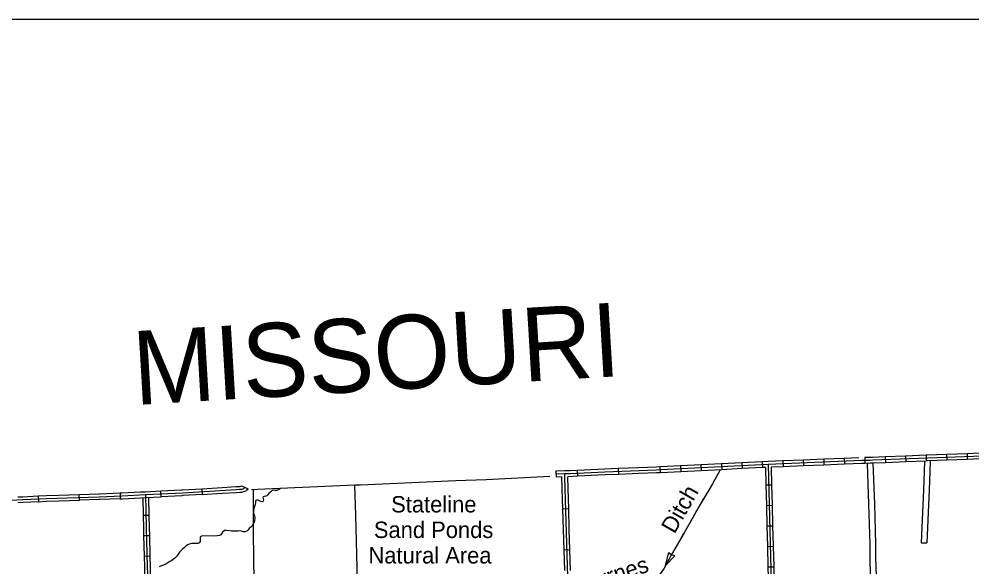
# Model space of a CAD drawing. Extents: x 1164457 to 1439835, y 1590918 to 1773502.
# Drawn here: x 1283501 to 1308056, y 1664462 to 1678582 of the extents above; entities that cross this region are included whole.
import ezdxf

# ---------------------------------------------------------------- set-up
doc = ezdxf.new("R2010")
doc.units = 0
for name, color, linetype in [('Level 1', 7, 'Continuous'), ('Level 30', 7, 'Continuous'), ('Level 31', 7, 'Continuous'), ('Level 32', 7, 'Continuous'), ('Level 35', 7, 'Continuous'), ('Level 43', 7, 'Continuous'), ('Level 45', 7, 'Continuous'), ('Level 46', 7, 'Continuous'), ('Level 7', 7, 'Continuous'), ('R_Draft', 7, 'Continuous')]:
    doc.layers.add(name, color=color, linetype=linetype)

msp = doc.modelspace()

# ---------------------------------------------------------------- linework, layer by layer
at = {"layer": 'Level 1'}
msp.add_lwpolyline([(1297182, 1666796), (1295539, 1666710), (1294754, 1666683), (1292299, 1666571), (1292152, 1666566), (1289647, 1666456), (1289493, 1666448)], dxfattribs=at)
at = {"layer": 'Level 31'}
for p, q in [((1286103, 1666369), (1286110, 1666219)), ((1287165, 1666272), (1287158, 1666421)), ((1288211, 1666479), (1288220, 1666329)), ((1283992, 1666292), (1284000, 1666143)), ((1285054, 1666180), (1285049, 1666330))]:
    msp.add_line(p, q, dxfattribs=at)
for points in [[(1278722, 1665984), (1279927, 1666021), (1281431, 1666097), (1281840, 1666107), (1282171, 1666122), (1283600, 1666197), (1284208, 1666228), (1285566, 1666271), (1286152, 1666296), (1286763, 1666327), (1287718, 1666374), (1289093, 1666457), (1289185, 1666463)], [(1285576, 1666347), (1286103, 1666369)], [(1286103, 1666369), (1286149, 1666371), (1286630, 1666395)], [(1286630, 1666395), (1286759, 1666402), (1287158, 1666421)], [(1287158, 1666421), (1287685, 1666448)], [(1287685, 1666448), (1287714, 1666449), (1288211, 1666479)], [(1288211, 1666479), (1288738, 1666511)], [(1288738, 1666511), (1289089, 1666532), (1289181, 1666537), (1289218, 1666540), (1289231, 1666549), (1289401, 1666471)], [(1288747, 1666361), (1289097, 1666382), (1289190, 1666388), (1289238, 1666391), (1289269, 1666397), (1289290, 1666404), (1289343, 1666426), (1289372, 1666445), (1289401, 1666471)], [(1289185, 1666463), (1289228, 1666465), (1289251, 1666470), (1289273, 1666477), (1289294, 1666487), (1289307, 1666504)], [(1283465, 1666265), (1283596, 1666272), (1283992, 1666292)], [(1284000, 1666143), (1283604, 1666122), (1283473, 1666115)], [(1283992, 1666292), (1284205, 1666303), (1284521, 1666313)], [(1284000, 1666143), (1284211, 1666153), (1284526, 1666163)], [(1284521, 1666313), (1285049, 1666330)], [(1284526, 1666163), (1285054, 1666180)], [(1285049, 1666330), (1285563, 1666346), (1285576, 1666347)], [(1285582, 1666197), (1285568, 1666196), (1285054, 1666180)], [(1286110, 1666219), (1285582, 1666197)], [(1286110, 1666219), (1286156, 1666221), (1286638, 1666245)], [(1286638, 1666245), (1286766, 1666252), (1287165, 1666272)], [(1287692, 1666298), (1287165, 1666272)], [(1288220, 1666329), (1287722, 1666299), (1287692, 1666298)], [(1288220, 1666329), (1288747, 1666361)]]:
    msp.add_lwpolyline(points, dxfattribs=at)
at = {"layer": 'Level 32'}
for p, q in [((1307403, 1667361), (1307409, 1667211)), ((1307931, 1667381), (1307936, 1667231)), ((1301599, 1667118), (1301607, 1666968)), ((1302127, 1667144), (1302134, 1666995)), ((1302654, 1667171), (1302661, 1667021)), ((1303182, 1667194), (1303188, 1667044)), ((1303710, 1667216), (1303716, 1667066)), ((1304237, 1667238), (1304243, 1667088)), ((1304765, 1667260), (1304771, 1667110)), ((1305293, 1667280), (1305297, 1667130)), ((1305820, 1667298), (1305826, 1667149)), ((1306348, 1667320), (1306354, 1667170)), ((1306875, 1667341), (1306881, 1667192)), ((1300016, 1667038), (1300026, 1666888)), ((1300545, 1667065), (1300552, 1666915)), ((1301072, 1667091), (1301079, 1666941)), ((1302745, 1666574), (1302895, 1666578)), ((1302758, 1666046), (1302908, 1666050)), ((1286698, 1665797), (1286848, 1665800)), ((1302771, 1665518), (1302921, 1665522)), ((1286709, 1665269), (1286859, 1665273)), ((1302785, 1664990), (1302934, 1664994)), ((1286723, 1664741), (1286872, 1664745)), ((1302798, 1664462), (1302948, 1664466))]:
    msp.add_line(p, q, dxfattribs=at)
for points in [[(1321119, 1667917), (1318832, 1667801), (1318254, 1667775), (1315826, 1667665), (1313323, 1667544), (1312931, 1667528), (1312880, 1667526), (1310607, 1667432), (1308095, 1667312), (1306907, 1667268), (1305501, 1667210), (1305435, 1667209), (1305218, 1667203), (1302807, 1667104), (1300037, 1666964), (1300001, 1666961)], [(1307403, 1667361), (1306904, 1667343), (1306875, 1667341)], [(1307931, 1667381), (1307403, 1667361)], [(1308457, 1667404), (1308092, 1667387), (1307931, 1667381)], [(1301599, 1667118), (1301072, 1667091)], [(1302127, 1667144), (1301599, 1667118)], [(1302654, 1667171), (1302127, 1667144)], [(1303182, 1667194), (1302803, 1667178), (1302654, 1667171)], [(1302807, 1667104), (1302959, 1661013), (1303033, 1658417), (1303054, 1657502), (1303073, 1656547), (1303091, 1655953), (1303095, 1655780), (1303144, 1653171), (1303204, 1650854), (1303207, 1650572)], [(1303710, 1667216), (1303182, 1667194)], [(1304237, 1667238), (1303710, 1667216)], [(1304765, 1667260), (1304237, 1667238)], [(1304771, 1667110), (1304243, 1667088)], [(1305144, 1667275), (1304765, 1667260)], [(1305297, 1667130), (1305220, 1667128), (1304771, 1667110)], [(1305820, 1667298), (1305498, 1667285), (1305433, 1667284), (1305293, 1667280)], [(1305826, 1667149), (1305503, 1667135), (1305437, 1667134), (1305297, 1667130)], [(1306348, 1667320), (1305820, 1667298)], [(1306354, 1667170), (1305826, 1667149)], [(1306875, 1667341), (1306348, 1667320)], [(1306881, 1667192), (1306354, 1667170)], [(1307409, 1667211), (1306910, 1667193), (1306881, 1667192)], [(1307936, 1667231), (1307409, 1667211)], [(1308464, 1667254), (1308099, 1667237), (1307936, 1667231)], [(1300545, 1667065), (1300033, 1667039), (1300016, 1667038)], [(1300552, 1666915), (1300042, 1666889), (1300026, 1666888)], [(1301072, 1667091), (1300545, 1667065)], [(1301079, 1666941), (1300552, 1666915)], [(1301607, 1666968), (1301079, 1666941)], [(1302134, 1666995), (1301607, 1666968)], [(1302661, 1667021), (1302134, 1666995)], [(1302734, 1667025), (1302661, 1667021)], [(1302734, 1667025), (1302745, 1666574)], [(1303188, 1667044), (1302884, 1667032)], [(1302884, 1667032), (1302895, 1666578)], [(1303716, 1667066), (1303188, 1667044)], [(1304243, 1667088), (1303716, 1667066)], [(1302745, 1666574), (1302758, 1666046)], [(1302895, 1666578), (1302908, 1666050)], [(1286689, 1666248), (1286698, 1665797)], [(1286763, 1666327), (1286779, 1665469), (1286805, 1664462), (1286808, 1664283)], [(1286839, 1666255), (1286848, 1665800)], [(1302758, 1666046), (1302771, 1665518)], [(1302908, 1666050), (1302921, 1665522)], [(1286698, 1665797), (1286704, 1665467), (1286709, 1665269)], [(1286848, 1665800), (1286854, 1665470), (1286859, 1665273)], [(1302771, 1665518), (1302785, 1664990)], [(1302921, 1665522), (1302934, 1664994)], [(1286709, 1665269), (1286723, 1664741)], [(1286859, 1665273), (1286872, 1664745)], [(1302785, 1664990), (1302798, 1664462)], [(1302934, 1664994), (1302948, 1664466)], [(1286723, 1664741), (1286730, 1664461), (1286733, 1664280), (1286737, 1664211)], [(1286872, 1664745), (1286880, 1664464), (1286883, 1664286), (1286887, 1664220)], [(1302798, 1664462), (1302811, 1663935)], [(1302948, 1664466), (1302961, 1663938)]]:
    msp.add_lwpolyline(points, dxfattribs=at)
at = {"layer": 'Level 35'}
msp.add_lwpolyline([(1290238, 1666482), (1290195, 1666455), (1290147, 1666434), (1290100, 1666432), (1290049, 1666439), (1290011, 1666423), (1289976, 1666393), (1289939, 1666358), (1289913, 1666322), (1289888, 1666297), (1289860, 1666283), (1289821, 1666279), (1289791, 1666273), (1289781, 1666252), (1289788, 1666225), (1289798, 1666193), (1289795, 1666158), (1289772, 1666139), (1289734, 1666146), (1289696, 1666168), (1289660, 1666186), (1289630, 1666187), (1289603, 1666176), (1289595, 1666163), (1289590, 1666119), (1289583, 1666067), (1289553, 1665969), (1289539, 1665901), (1289546, 1665850), (1289567, 1665779), (1289580, 1665727), (1289567, 1665642), (1289524, 1665545), (1289500, 1665509), (1289473, 1665489), (1289434, 1665457), (1289400, 1665413), (1289371, 1665384), (1289327, 1665366), (1289286, 1665371), (1289232, 1665384), (1289189, 1665389), (1289149, 1665386), (1289108, 1665381), (1288974, 1665383), (1288931, 1665389), (1288837, 1665403), (1288813, 1665406), (1288794, 1665398), (1288746, 1665357), (1288703, 1665293), (1288666, 1665270), (1288603, 1665266), (1288518, 1665257), (1288254, 1665264), (1288200, 1665257), (1288184, 1665248), (1288172, 1665234), (1288166, 1665202), (1288168, 1665114), (1288138, 1665086), (1288110, 1665070), (1287949, 1665063), (1287881, 1665052), (1287848, 1665035), (1287803, 1665004), (1287764, 1664967), (1287713, 1664922), (1287637, 1664839), (1287566, 1664742), (1287519, 1664690), (1287439, 1664624), (1287390, 1664603), (1287280, 1664535), (1287211, 1664504), (1287112, 1664461)], dxfattribs=at)
at = {"layer": 'Level 43'}
for p, q in [((1300163, 1664503), (1300249, 1664836)), ((1300163, 1664503), (1300403, 1664748)), ((1300249, 1664836), (1300314, 1664772)), ((1300403, 1664748), (1300315, 1664771))]:
    msp.add_line(p, q, dxfattribs=at)
for points in [[(1301572, 1666966), (1301374, 1666606), (1301255, 1666413), (1301049, 1666067), (1300639, 1665343), (1300343, 1664822), (1300121, 1664430), (1300047, 1664318), (1300013, 1664279), (1299978, 1664242), (1299925, 1664200), (1299878, 1664169), (1299752, 1664120), (1298199, 1663579)], [(1301572, 1666966), (1301477, 1666793)], [(1301413, 1666677), (1301374, 1666606), (1301255, 1666413), (1301210, 1666337)], [(1301143, 1666224), (1301049, 1666067), (1300944, 1665881)], [(1300879, 1665766), (1300684, 1665422)], [(1300618, 1665307), (1300423, 1664963)], [(1300358, 1664848), (1300343, 1664822), (1300163, 1664503)]]:
    msp.add_lwpolyline(points, dxfattribs=at)
at = {"layer": 'Level 45'}
for p, q in [((1297887, 1666948), (1297894, 1666798)), ((1298942, 1666997), (1298948, 1666847)), ((1297665, 1665957), (1297515, 1665953)), ((1297697, 1664902), (1297547, 1664897))]:
    msp.add_line(p, q, dxfattribs=at)
for points in [[(1297360, 1666929), (1297337, 1666928), (1297342, 1666778)], [(1300001, 1666961), (1299922, 1666960), (1298598, 1666908), (1297708, 1666864), (1297565, 1666860), (1297340, 1666853)], [(1297887, 1666948), (1297705, 1666939), (1297563, 1666935), (1297360, 1666929)], [(1297686, 1662789), (1297566, 1666767), (1297565, 1666801), (1297565, 1666860)], [(1298414, 1666974), (1297887, 1666948)], [(1298942, 1666997), (1298595, 1666983), (1298414, 1666974)], [(1299470, 1667017), (1298942, 1666997)], [(1299476, 1666867), (1298948, 1666847)], [(1300016, 1667038), (1299920, 1667035), (1299470, 1667017)], [(1300026, 1666888), (1299925, 1666885), (1299476, 1666867)], [(1297490, 1666783), (1297342, 1666778)], [(1297499, 1666481), (1297490, 1666783)], [(1297894, 1666798), (1297640, 1666785)], [(1297649, 1666485), (1297640, 1666785)], [(1298422, 1666824), (1297894, 1666798)], [(1298948, 1666847), (1298601, 1666833), (1298422, 1666824)], [(1297515, 1665953), (1297499, 1666481)], [(1297665, 1665957), (1297649, 1666485)], [(1297531, 1665425), (1297515, 1665953)], [(1297681, 1665430), (1297665, 1665957)], [(1297547, 1664897), (1297531, 1665425)], [(1297697, 1664902), (1297681, 1665430)], [(1297563, 1664370), (1297547, 1664897)], [(1297713, 1664374), (1297697, 1664902)]]:
    msp.add_lwpolyline(points, dxfattribs=at)
at = {"layer": 'Level 46'}
for points in [[(1305465, 1663245), (1305444, 1664211), (1305432, 1664710), (1305431, 1665053), (1305402, 1666084), (1305363, 1667132)], [(1305615, 1663248), (1305594, 1664214), (1305582, 1664712), (1305581, 1665055), (1305552, 1666089), (1305513, 1667136)], [(1306833, 1667190), (1306824, 1666924), (1306804, 1666451), (1306747, 1665086), (1306897, 1665080)], [(1306983, 1667195), (1306974, 1666918), (1306954, 1666445), (1306897, 1665080)]]:
    msp.add_lwpolyline(points, dxfattribs=at)
at = {"layer": 'Level 7'}
msp.add_lwpolyline([(1292143, 1666565), (1292169, 1665796), (1292215, 1664114), (1289562, 1664067), (1289545, 1665348), (1289541, 1666450)], dxfattribs=at)
at = {"layer": 'R_Draft'}
msp.add_lwpolyline([(1246398, 1678582), (1349820, 1678582), (1349820, 1614471), (1246398, 1614471)], close=True, dxfattribs=at)

# ---------------------------------------------------------------- texts
at = {"layer": 'Level 30'}
msp.add_text('MISSOURI', height=1900.8, rotation=3.4119, dxfattribs=at).set_placement((1286487, 1668634))
at = {"layer": 'Level 43'}
for s, rotation, p in [('Ditch', 60.2555, (1300391, 1665294)), ('Byrnes', 18.1495, (1298092, 1663803))]:
    msp.add_text(s, height=422, rotation=rotation, dxfattribs=at).set_placement(p)
at = {"layer": 'Level 7'}
for s, p in [('Stateline', (1293090, 1665866)), ('Sand Ponds', (1292644, 1665208)), ('Natural Area', (1292505, 1664551))]:
    msp.add_text(s, height=422.4, dxfattribs=at).set_placement(p)

doc.saveas('drawing.dxf')
